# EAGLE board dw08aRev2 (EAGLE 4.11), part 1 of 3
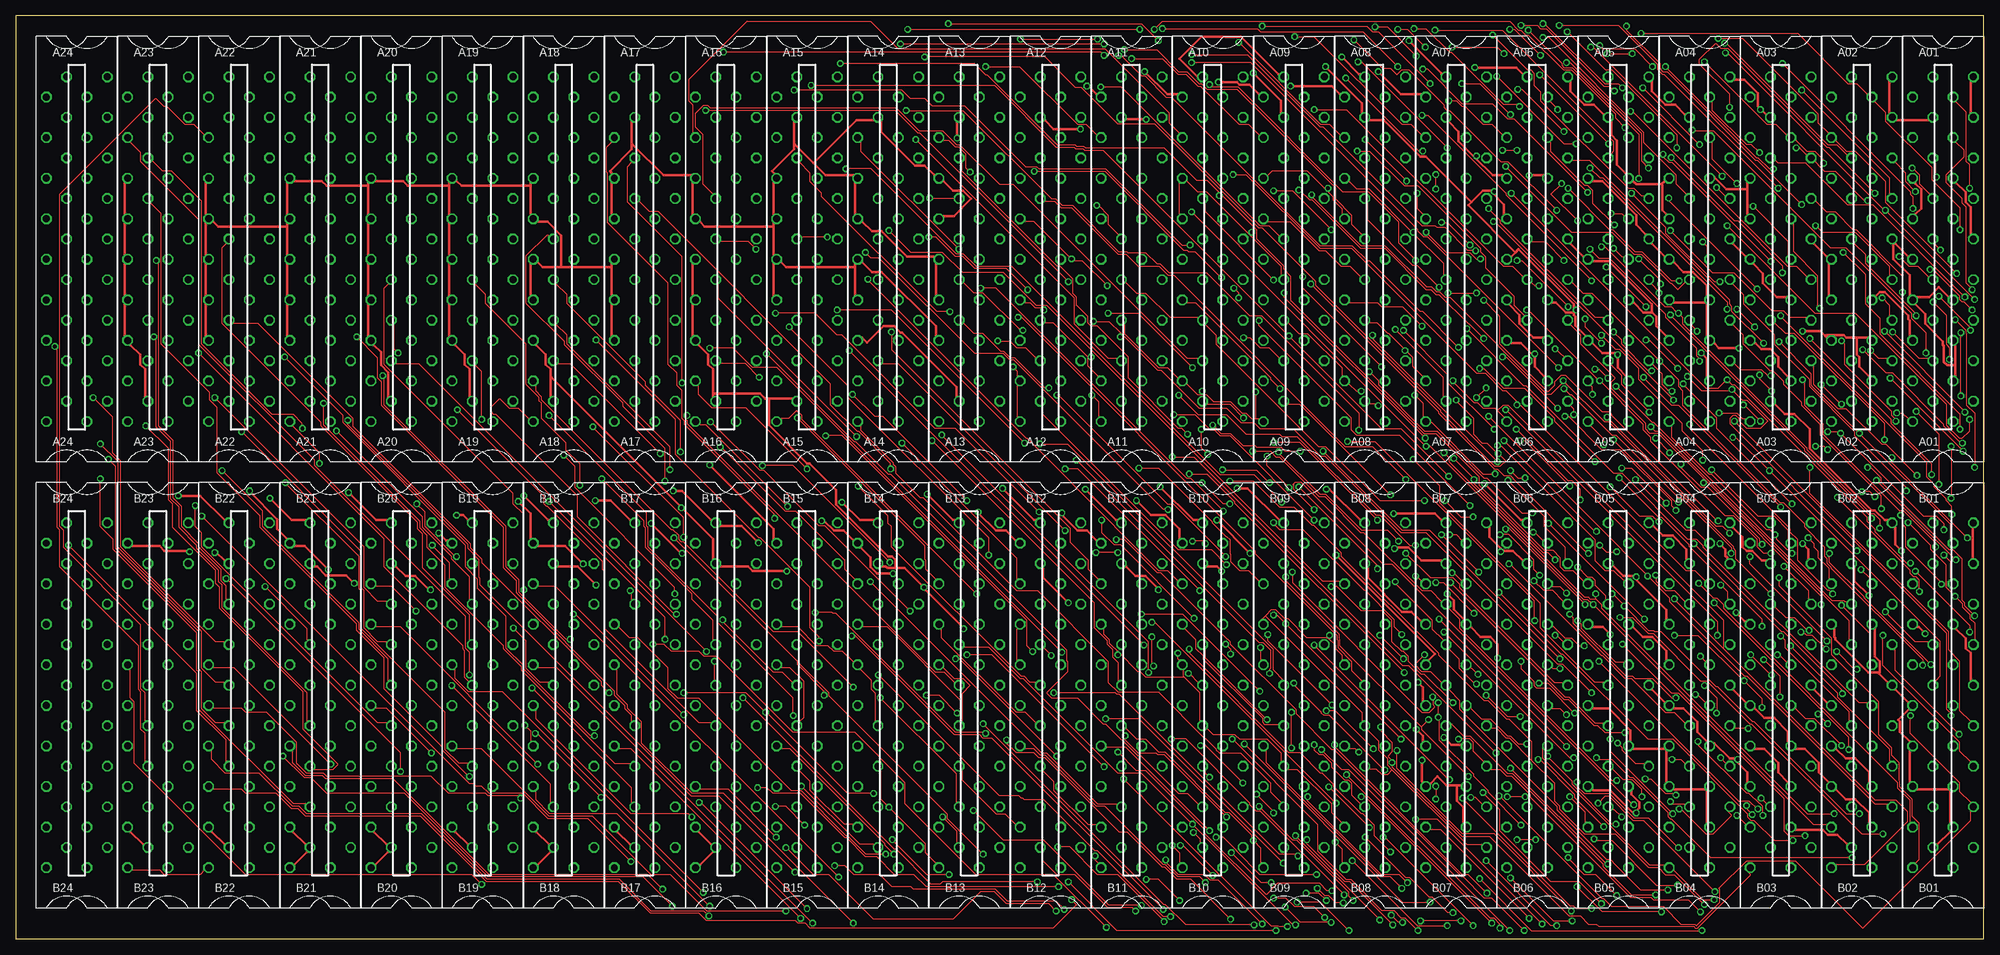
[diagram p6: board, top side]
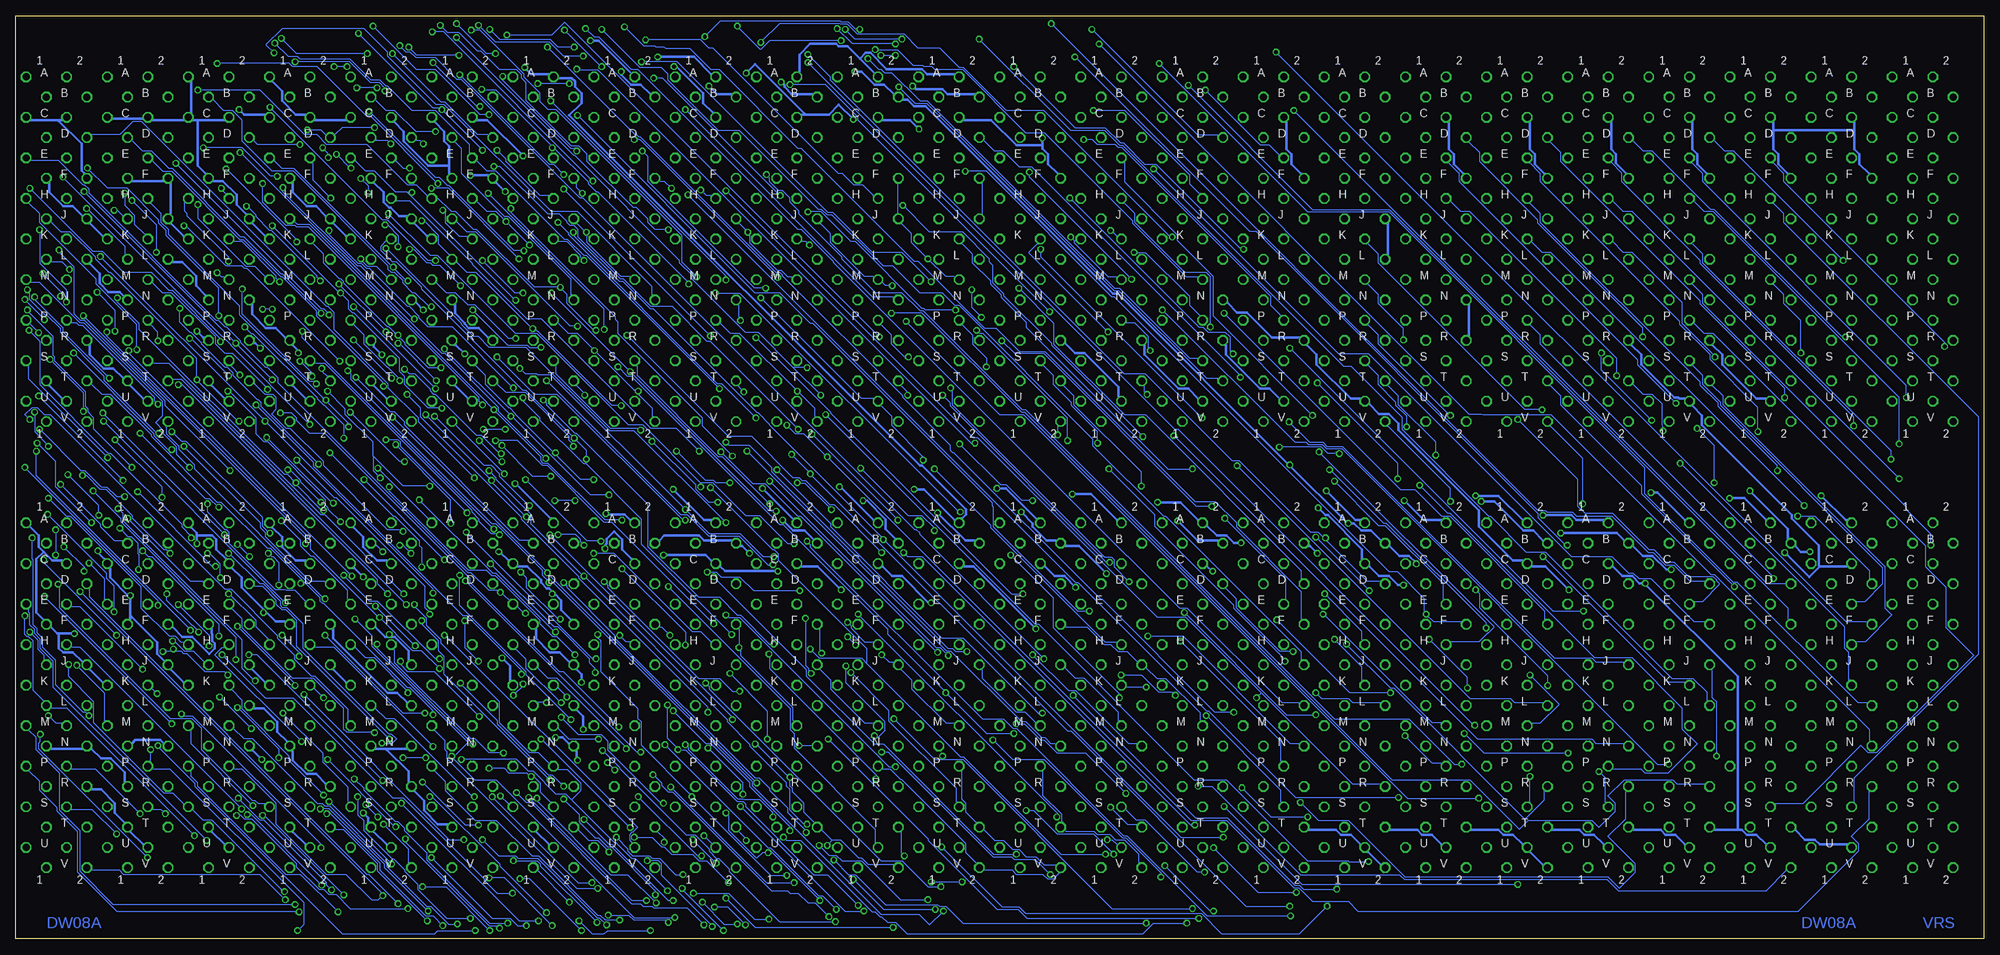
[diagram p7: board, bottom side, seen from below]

Size 307.98 x 144.46 mm. Coordinates in mm from the lower left corner, seen from the top.
Outline: 0,0 307.98,0 307.98,144.46 0,144.46 0,0
Copper layers (1*16): Top 0.035mm / dielectric 1.5mm / Bottom 0.035mm
Design rules "sierraproto": minimum track width 6mil, minimum drill 24mil, track to track 6mil, track to pad 6mil, pad to pad 10mil, via to via 6mil, smd to smd 6mil, copper to edge 25mil, drill to drill 10mil, minimum pad ring 10mil, minimum via ring 8mil, stop-mask expansion 0mil, vias tented up to drill 0mil, thermal gap 10mil
Net classes: 1 supply: width 0.381 mm

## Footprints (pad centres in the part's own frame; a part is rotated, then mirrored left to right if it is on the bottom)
H807 = drill 1.092 octagon: A1 4.763,28.575; A2 -1.587,28.575; B1 1.587,25.4; B2 -4.763,25.4; C1 4.763,22.225; C2 -1.587,22.225; D1 1.587,19.05; D2 -4.763,19.05; E1 4.763,15.875; E2 -1.587,15.875; F1 1.587,12.7; F2 -4.763,12.7; H1 4.763,9.525; H2 -1.587,9.525; J1 1.587,6.35; J2 -4.763,6.35; K1 4.763,3.175; K2 -1.587,3.175; L1 1.587,0; L2 -4.763,0; M1 4.763,-3.175; M2 -1.587,-3.175; N1 1.587,-6.35; N2 -4.763,-6.35; P1 4.763,-9.525; P2 -1.587,-9.525; R1 1.587,-12.7; R2 -4.763,-12.7; S1 4.763,-15.875; S2 -1.587,-15.875; T1 1.587,-19.05; T2 -4.763,-19.05; U1 4.763,-22.225; U2 -1.587,-22.225; V1 1.587,-25.4; V2 -4.763,-25.4

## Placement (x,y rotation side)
A01  M903  [H807]  301.62,106.36 0 top
A02  M903  [H807]  288.93,106.36 0 top
A03  M903  [H807]  276.23,106.36 0 top
A04  M903  [H807]  263.52,106.36 0 top
A05  M903  [H807]  250.82,106.36 0 top
A06  M907  [H807]  238.12,106.36 0 top
A07  M651  [H807]  225.43,106.36 0 top
A08  M651  [H807]  212.72,106.36 0 top
A09  M651  [H807]  200.03,106.36 0 top
A10  M651  [H807]  187.32,106.36 0 top
A11  M651  [H807]  174.62,106.36 0 top
A12  M651  [H807]  161.93,106.36 0 top
A13  W011  [H807]  149.22,106.36 0 top
A14  W011  [H807]  136.53,106.36 0 top
A15  W011  [H807]  123.83,106.36 0 top
A16  W011  [H807]  111.12,106.36 0 top
A17  W011  [H807]  98.42,106.36 0 top
A18  W011  [H807]  85.72,106.36 0 top
A19  W011  [H807]  73.03,106.36 0 top
A20  W011  [H807]  60.33,106.36 0 top
A21  W011  [H807]  47.62,106.36 0 top
A22  W011  [H807]  34.92,106.36 0 top
A23  W011  [H807]  22.23,106.36 0 top
A24  H807  [H807]  9.53,106.36 0 top
B01  M903  [H807]  301.62,36.51 0 top
B02  M903  [H807]  288.93,36.51 0 top
B03  M903  [H807]  276.23,36.51 0 top
B04  M903  [H807]  263.52,36.51 0 top
B05  M903  [H807]  250.82,36.51 0 top
B06  M101  [H807]  238.12,36.51 0 top
B07  M907  [H807]  225.43,36.51 0 top
B08  M651  [H807]  212.72,36.51 0 top
B09  M651  [H807]  200.03,36.51 0 top
B10  M651  [H807]  187.32,36.51 0 top
B11  M651  [H807]  174.62,36.51 0 top
B12  M651  [H807]  161.93,36.51 0 top
B13  M651  [H807]  149.22,36.51 0 top
B14  M651  [H807]  136.53,36.51 0 top
B15  M651  [H807]  123.83,36.51 0 top
B16  M517  [H807]  111.12,36.51 0 top
B17  M517  [H807]  98.42,36.51 0 top
B18  M517  [H807]  85.72,36.51 0 top
B19  M517  [H807]  73.03,36.51 0 top
B20  M517  [H807]  60.33,36.51 0 top
B21  M517  [H807]  47.62,36.51 0 top
B22  M517  [H807]  34.92,36.51 0 top
B23  M517  [H807]  22.23,36.51 0 top
B24  H807  [H807]  9.53,36.51 0 top

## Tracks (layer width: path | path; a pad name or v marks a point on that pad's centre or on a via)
-15V  (via drill 0.61)
  Top 0.381: v126.11,65.41 126.49,65.41 128.02,63.88 129.54,63.88 131.06,62.36 B14.B2 132.21,61.21 133.73,59.69 133.73,58.17 134.75,57.15 v137.29,57.15 | v163.7,66.67 163.7,66.29 166.12,63.88 167.64,63.88 169.16,62.36 B11.B2 | v175.39,68.58 177.67,66.29 179.96,66.29 182.12,64.14 182.12,62.61 B10.B2 | v193.17,60.33 v187.96,65.53 | v150.62,66.8 150.62,66.67 153.42,63.88 154.94,63.88 156.46,62.36 B12.B2 | v167.64,133.48 167.89,133.48 169.16,132.21 A11.B2 | v176.66,135.76 180.21,132.21 181.86,132.21 A10.B2 | v199.52,133.48 205.99,133.48 207.26,132.21 A08.B2 | v213.23,135.76 216.79,132.21 219.96,132.21 A07.B2 | v188.21,134.11 191.13,134.11 191.52,133.73 193.04,133.73 194.56,132.21 A09.B2 | v88.77,58.67 85.98,61.47 81.66,61.47 B18.B2 80.52,62.61 80.52,66.55 v78.61,68.45 | v104.27,60.33 104.14,60.33 v99.44,65.02 | v27.18,60.58 27.05,60.71 23.24,60.71 22.48,61.47 18.16,61.47 B23.B2 | v48.9,57.78 45.21,61.47 43.56,61.47 B21.B2 42.42,62.61 40.89,64.14 40.89,65.66 36.58,69.98 v36.58,70.1 | v66.17,63.5 67.31,62.36 67.56,62.36 B19.B2 | v108.58,74.17 118.62,64.14 118.62,62.61 B15.B2
  Bottom 0.381: v126.11,65.41 123.06,62.36 119.76,62.36 B15.B2 | v137.29,57.15 141.6,61.47 143.76,61.47 B13.B2 145.16,62.36 146.69,62.36 148.84,64.52 148.84,65.02 v150.62,66.8 | B08.B2 207.26,62.36 206.5,63.12 201.04,63.12 200.28,62.36 195.96,62.36 B09.B2 194.56,61.47 194.31,61.47 v193.17,60.33 | v163.7,66.67 159.38,62.36 157.86,62.36 B12.B2 | v175.39,68.58 174.75,68.58 171.83,65.66 171.83,64.14 170.31,62.61 B11.B2 | v187.96,65.53 186.31,63.88 184.53,63.88 B10.B2 | v167.64,133.48 167.13,132.97 162.94,132.97 162.18,132.21 157.86,132.21 A12.B2 | v176.66,135.76 175.64,135.76 173.61,133.73 172.09,133.73 170.56,132.21 A11.B2 169.16,131.32 168.4,131.32 167.39,130.3 165.61,130.3 136.27,100.97 135.51,100.97 108.65,74.11 | v199.52,133.48 198.25,132.21 195.96,132.21 A09.B2 | v213.23,135.76 213.23,135.25 211.71,133.73 210.19,133.73 208.66,132.21 A08.B2 | v188.21,134.11 187.71,133.6 187.71,133.35 186.56,132.21 183.26,132.21 A10.B2 | v88.77,58.67 88.77,58.8 89.92,59.94 91.44,59.94 92.96,61.47 B17.B2 94.36,62.36 95.89,63.88 97.41,63.88 98.55,65.02 v99.44,65.02 99.82,65.28 108.65,74.11 | v104.27,60.33 105.41,61.47 105.66,61.47 B16.B2 | v27.18,60.58 28.57,60.58 29.46,61.47 B22.B2 30.61,62.61 30.61,64.14 v36.58,70.1 | v48.9,57.78 49.66,57.78 51.82,59.94 53.34,59.94 54.86,61.47 B20.B2 56.26,62.36 57.4,63.5 v66.17,63.5 | v78.61,68.45 76.58,68.45 72.01,63.88 70.48,63.88 68.96,62.36 B19.B2 | v108.58,74.17 108.65,74.11
A06U1  (via drill 0.61)
  Top 0.152: 205.1,117.22 202.18,120.14 196.6,120.14 195.96,119.51 A09.F2 | 205.1,117.22 206.12,116.2 206.12,115.7 207.52,114.3 207.52,113.41 A08.J2 | v205.36,117.47 205.1,117.22 | 218.69,110.49 211.84,117.35 209.93,117.35 208.66,118.62 A08.F2 | 218.69,110.49 223.39,105.79 223.39,103.89 A07.M2 | v219.33,116.71 219.33,114.3 220.22,113.41 A07.J2 | A09.J2 195.96,112.27 199.39,112.27 203.96,107.7 204.98,107.7 207.39,105.28 208.79,105.28 210.44,103.63 A08.M2 | v218.69,110.62 218.69,110.49 | v233.55,71.75 239.14,66.17 239.14,64.64 242.44,61.34 242.44,59.44 B06.C1 | v243.84,82.04 243.84,82.93 243.33,83.44 A06.U1 | A12.J2 157.86,112.27 159.38,112.27 v165.23,106.43 165.61,106.17 166.88,106.17 v170.81,102.23 | A11.M2 173.74,102.74 175.39,101.09 176.78,101.09 180.59,97.28 185.04,97.28 A10.P2 186.18,96.14 187.83,94.49 187.83,93.09 203.84,77.09 204.98,77.09 213.49,68.58 v220.47,68.58 | A10.J2 182.12,113.41 182.12,118.36 A10.F2 183.26,118.62 184.91,116.97 186.31,116.97 193.04,110.24 | 193.04,110.24 197.99,105.28 197.99,103.89 A09.M2 | v228.09,66.04 226.19,66.04 v223.65,68.58 | 193.04,110.24 v193.42,110.62
  Bottom 0.152: v205.36,117.47 206.5,118.62 207.26,118.62 A08.F2 | A10.M2 186.44,103.63 187.2,103.63 188.21,104.65 188.85,104.65 193.17,108.97 193.17,110.36 v193.42,110.62 194.82,112.01 A09.J2 | 218.82,110.62 220.22,112.01 A07.J2 | 218.82,110.62 218.57,110.36 218.57,108.97 213.23,103.63 211.84,103.63 A08.M2 | v219.33,116.71 220.22,117.6 220.22,118.36 A07.F2 | 218.82,110.62 v218.69,110.62 | v243.84,82.04 v233.55,71.75 233.3,71.37 233.3,71.25 v228.09,66.04 | A12.J2 156.72,113.41 156.72,118.36 A12.F2 | A12.M2 161.04,103.63 162.43,103.63 v165.23,106.43 167.77,108.97 167.77,110.36 169.42,112.01 A11.J2 169.93,113.41 169.93,118.36 A11.F2 | A10.J2 182.12,112.01 180.47,110.36 180.47,108.97 175.13,103.63 173.74,103.63 A11.M2 172.34,102.74 171.83,102.23 v170.81,102.23 | v220.47,68.58 v223.65,68.58
A06V1  (via drill 0.61)
  Top 0.152: v218.95,85.09 220.22,83.82 220.22,81.66 A07.V2 221.36,81.03 229.62,72.77 v231.52,72.77 | 217.42,92.2 218.57,91.06 218.57,89.66 220.22,88.01 A07.T2 | 217.42,92.2 214.88,94.74 214.76,94.74 213.11,96.39 211.84,96.39 A08.P2 | v217.42,92.08 217.42,92.2 | A09.P2 199.14,96.39 200.79,94.74 202.18,94.74 207.52,89.41 207.52,88.01 A08.T2 208.66,86.87 209.8,85.72 v210.57,85.72 | A12.V2 156.72,81.66 156.72,86.61 A12.T2 156.72,88.01 156.72,88.9 v156.08,89.53 | v168.4,85.09 169.42,84.07 169.42,81.66 A11.V2 | 167.77,91.06 162.43,96.39 161.04,96.39 A12.P2 | 167.77,91.06 167.77,89.66 169.42,88.01 A11.T2 | 194.06,81.41 193.42,81.41 192.53,82.3 191.9,82.3 190.12,84.07 187.45,84.07 186.31,85.22 185.67,85.22 | 194.06,81.41 194.56,81.41 A09.V2 | 185.67,85.22 184.91,85.22 183.26,86.87 A10.T2 181.86,87.76 180.21,89.41 178.82,89.41 173.48,94.74 173.48,96.14 A11.P2 | 194.06,81.41 v194.06,85.6 | 167.77,91.06 v168.28,91.06 | 185.67,85.22 v185.67,85.72
  Bottom 0.152: 210.82,85.47 v217.42,92.08 220.09,94.74 221.49,94.74 223.14,96.39 A07.P2 | 210.82,85.47 208.41,83.06 208.41,81.66 A08.V2 | v218.95,85.09 218.95,85.34 220.22,86.61 A07.T2 | v231.52,72.77 A06.V1 | A10.V2 183.01,81.66 183.01,83.06 v185.67,85.72 194.69,94.74 196.09,94.74 197.74,96.39 A09.P2 | v168.4,85.09 168.4,85.6 169.42,86.61 A11.T2 | v156.08,89.53 156.08,90.93 158.24,93.09 158.24,94.49 159.89,96.14 A12.P2 | v194.06,85.6 194.82,86.36 194.82,86.61 A09.T2 | v168.28,91.06 168.91,91.06 170.94,93.09 170.94,94.49 172.59,96.14 A11.P2 | v210.57,85.72 210.82,85.47
B07U1  (via drill 0.61)
  Top 0.152: B14.M2 134.49,34.04 134.49,38.48 133.86,39.12 133.86,40.51 132.21,42.16 B14.J2 131.06,43.31 129.41,44.96 128.02,44.96 127.13,45.85 125.35,45.85 122.43,48.77 119.76,48.77 B15.F2 | B15.J2 119.76,42.42 121.16,42.42 123.32,40.26 123.32,34.67 122.68,34.04 B15.M2 | B12.J2 156.72,43.56 156.72,48.51 B12.F2 | 148.08,37.08 148.08,38.35 149.35,39.62 148.21,40.77 146.81,40.77 145.16,42.42 B13.J2 | 148.08,37.08 148.08,34.04 B13.M2 | 148.08,37.08 136.4,48.77 132.46,48.77 B14.F2 | 215.39,26.42 214.63,25.65 213.87,25.65 212.98,26.54 211.84,26.54 B08.P2 | 215.39,26.42 214.63,27.18 214.63,28.19 213.23,29.59 213.23,30.99 211.58,32.64 B08.M2 210.69,34.04 210.69,35.43 195.58,50.55 | 215.39,26.42 227.08,14.73 229.49,14.73 B07.U1 | B09.M2 197.74,33.53 195.45,33.53 195.07,33.91 195.07,34.54 185.8,43.81 185.8,44.32 184.66,45.47 184.66,46.86 183.01,48.51 B10.F2 | v206.5,15.11 207.52,14.1 207.52,11.81 B08.V2 | B08.T2 207.52,18.16 205.87,19.81 205.87,21.21 200.53,26.54 199.14,26.54 B09.P2 197.99,27.69 197.99,29.08 195.83,31.24 191.52,31.24 190.75,32 187.32,32 186.44,32.89 B10.M2 185.29,34.04 185.29,38.48 182.88,40.89 | v194.82,45.59 194.82,43.56 B09.J2 | 205.23,47.12 202.06,47.12 199.14,50.04 198.63,50.04 197.23,51.44 196.47,51.44 195.58,50.55 | 205.23,47.12 205.36,47.12 206.5,45.97 206.5,45.47 207.52,44.45 207.52,43.56 B08.J2 | 195.58,50.55 194.94,49.91 B09.F2 | v205.61,47.5 205.23,47.12 | B09.V2 194.82,11.81 194.82,14.22 v193.68,15.37 193.42,15.75 193.42,16.26 189.87,19.81 189.23,19.81 179.83,29.21 178.82,29.21 176.78,31.24 175.39,31.24 173.74,32.89 B11.M2
  Top 0.152: 182.88,40.89 182.75,41.02 182.75,42.16 B10.J2 182.12,43.56 181.86,43.81 v181.86,44.7 | 172.72,44.7 175.64,41.78 176.02,41.78 176.91,40.89 182.88,40.89 | 172.72,44.7 171.2,46.23 171.2,46.74 170.31,47.62 170.31,48.51 B11.F2 | 172.72,44.7 v172.47,44.45 | B13.F2 144.91,48.51 144.91,47.12 156.59,35.43 157.99,35.43 159.64,33.78 B12.M2
  Bottom 0.152: B15.M2 122.68,34.04 122.68,35.43 128.02,40.77 129.41,40.77 131.06,42.42 B14.J2 132.46,43.31 134.11,44.96 135.51,44.96 136.65,46.1 137.67,46.1 140.34,48.77 143.76,48.77 B13.F2 | B12.J2 156.72,42.16 156.72,40.77 151.38,35.43 149.99,35.43 148.34,33.78 B13.M2 | B14.M2 135.38,34.04 135.38,35.43 140.72,40.77 142.11,40.77 143.76,42.42 B13.J2 | v206.5,15.11 206.5,15.75 207.52,16.76 B08.T2 | B09.F2 194.82,48.51 v194.82,45.59 194.56,45.21 194.56,44.32 186.44,36.2 186.44,34.29 186.18,34.04 B10.M2 | v205.61,47.5 206.88,48.77 207.26,48.77 B08.F2 | B12.M2 161.04,33.78 162.43,33.78 167.77,39.12 167.77,40.51 169.42,42.16 B11.J2 170.56,43.31 171.32,43.31 v172.47,44.45 | v193.68,15.37 193.68,15.62 194.82,16.76 B09.T2 | B11.M2 173.74,33.78 175.13,33.78 180.47,39.12 180.47,40.51 182.12,42.16 B10.J2 | v181.86,44.7 182.12,44.96 182.12,48.51 B10.F2
B07V1  (via drill 0.61)
  Top 0.152: B14.T2 131.06,17.91 129.67,17.91 124.33,23.24 124.33,24.64 122.68,26.29 B15.P2 | B14.P2 135.38,26.29 135.38,21.84 v136.65,20.57 142.37,14.86 142.37,13.46 144.02,11.81 B13.V2 | B11.T2 169.16,17.91 167.77,17.91 162.43,23.24 162.43,24.64 160.78,26.29 B12.P2 | B13.P2 148.08,26.29 148.08,24.89 153.42,19.56 154.81,19.56 156.46,17.91 B12.T2 | v180.97,14.61 182.12,13.46 182.12,11.81 B10.V2 | v186.82,25.27 186.18,25.91 186.18,26.29 B10.P2 | v221.36,5.71 217.04,5.71 v192.28,30.48 | v168.91,12.95 168.91,12.32 169.42,11.81 B11.V2
  Bottom 0.152: B14.V2 132.21,11.81 132.21,13.21 134.37,15.37 135.76,15.37 136.65,16.26 138.68,16.26 139.19,16.76 143.51,16.76 143.76,17.02 B13.T2 144.27,18.16 144.27,19.43 147.19,22.35 147.19,26.29 B13.P2 | B12.P2 159.89,26.29 159.89,21.84 159.26,21.21 159.26,19.81 157.61,18.16 B12.T2 156.46,17.02 154.81,15.37 153.42,15.37 152.02,13.97 151,13.97 149.86,12.83 148.34,12.83 147.07,11.56 145.16,11.56 B13.V2 144.53,10.41 145.67,9.27 146.43,9.27 147.19,10.03 151.38,10.03 152.02,10.67 156.46,10.67 B12.V2 157.61,11.81 159.26,13.46 159.26,14.86 169.29,24.89 169.42,24.89 171.07,26.54 172.34,26.54 B11.P2 | v136.65,20.57 133.99,17.91 132.46,17.91 B14.T2 | 180.21,15.37 178.82,15.37 176.02,12.57 175.51,12.57 174.5,11.56 170.56,11.56 B11.V2 | 180.21,15.37 181.86,17.02 B10.T2 183.01,18.16 184.66,19.81 184.66,21.21 186.44,22.99 186.44,23.5 186.82,23.88 v186.82,25.27 187.2,25.53 192.15,30.48 v192.28,30.48 | 180.21,15.37 v180.97,14.61 | v221.36,5.71 226.31,10.67 B07.V1 | v168.91,12.95 169.42,13.46 169.42,16.76 B11.T2
GND  (via drill 0.61)
  Top 0.381: B16.V2 107.06,11.56 109.09,13.59 B16.U2 108.84,14.73 106.81,16.76 B16.T2 | B17.T2 94.11,16.76 96.14,14.73 B17.U2 | B18.V2 81.66,11.56 83.69,13.59 B18.U2 83.44,14.73 81.41,16.76 B18.T2 | B19.T2 68.71,16.76 70.74,14.73 B19.U2 | B20.V2 56.26,11.56 58.29,13.59 B20.U2 58.04,14.73 56.01,16.76 B20.T2 | B21.V2 43.56,11.56 45.59,13.59 B21.U2 45.34,14.73 43.31,16.76 B21.T2 | B23.U2 19.94,14.73 17.91,16.76 B23.T2 | B22.T2 30.61,16.76 32.64,14.73 B22.U2 | 232.66,60.83 232.79,60.71 234.31,60.71 235.84,59.18 B06.C2 | 232.66,60.83 230.63,62.87 230.63,64.39 B07.A1 | B08.C2 211.58,58.04 211.58,56.52 216.92,51.18 218.44,51.18 219.96,49.66 B07.F2 | v215.77,61.09 215.9,61.21 217.93,61.21 219.96,59.18 223.14,59.18 B07.C2 | v232.41,60.58 232.66,60.83 | 225.55,24 226.31,24 B07.R1 | 225.55,24 223.9,24 222.5,25.4 221.36,24.26 B07.R2 220.22,24.51 220.09,24.64 v220.09,27.94 | v223.52,31.5 224.66,30.35 226.31,30.35 B07.N1 | B07.T1 226.57,18.16 226.57,20.57 225.55,21.59 225.55,24 | v219.46,40.13 220.22,39.37 220.22,37.21 B07.L2 | v231.9,43.94 231.9,46.1 230.76,47.24 229.24,47.24 227.71,48.77 B07.F1 226.69,49.91 225.04,51.56 225.04,52.96 v224.03,53.98 | v219.2,32.77 220.22,31.75 220.22,30.86 B07.N2 | v188.72,57.53 187.96,58.29 186.44,58.29 B10.C2 | v164.72,52.58 160.78,56.52 160.78,58.04 B12.C2 | v178.82,54.61 178.82,54.74 176.78,56.77 175.26,56.77 173.74,58.29 B11.C2 | v52.96,55.63 51.69,56.9 48.51,56.9 47.12,58.29 46.74,58.29 B21.C2 | v64.9,54.61 64.64,54.61 62.48,56.77 60.96,56.77 59.44,58.29 B20.C2 | 137.67,58.04 139.06,58.04 v142.11,54.99 142.37,54.61 148.34,48.64 v148.34,48.51
  Top 0.381: 137.67,58.04 136.4,58.04 136.14,58.29 135.64,58.29 B14.C2 | A16.L2 105.92,105.66 105.92,100.71 A16.N2 105.92,99.31 105.92,94.36 A16.R2 106.81,92.96 108.33,91.44 108.33,89.92 109.09,89.15 109.09,85.34 | 109.09,85.34 109.09,84.84 A16.U2 | 117.86,84.58 117.22,84.58 116.46,85.34 109.09,85.34 | 117.86,84.58 121.54,84.58 A15.U2 | A13.U2 147.19,84.84 147.19,86.36 138.68,94.87 138.43,94.87 137.41,95.89 135.76,95.89 133.22,93.34 132.46,94.11 A14.R2 | 137.67,58.04 137.67,59.31 137.16,59.82 136.53,59.82 128.4,67.94 128.4,70.23 124.21,74.42 123.83,74.42 117.86,80.39 117.86,84.58 | v206.63,60.07 222.12,44.58 221.11,43.56 B07.J2 | B03.K1 281.43,38.99 283.46,36.96 B02.L2 | v290.07,53.72 287.78,56.01 287.78,58.04 B02.C2 | v295.15,60.71 294.13,61.72 294.13,64.39 B02.A1 292.99,65.53 292.48,65.53 290.96,67.06 290.45,67.06 280.8,76.71 280.8,79.76 278.38,82.17 276.86,82.17 275.34,83.69 A03.U2 | B01.C1 306.32,59.44 306.32,64.39 B01.A1 | v298.83,47.75 297.81,48.77 297.56,48.77 B01.F2 | B01.K1 305.94,40.39 305.94,44.7 305.18,45.47 305.18,46.99 303.66,48.51 B01.F1 | 291.59,41.53 292.99,40.13 B02.K1 294.13,38.99 296.16,36.96 B01.L2 294.64,34.29 294.89,34.04 294.89,32.38 296.42,30.86 B01.N2 296.42,29.46 296.42,24.51 B01.R2 297.56,23.37 302.51,23.37 B01.R1 302.77,23.11 302.77,18.16 B01.T1 302.77,16.76 300.74,14.73 B01.U2 | 291.59,41.53 291.46,41.66 289.94,41.66 284.73,46.86 284.73,47.12 284.61,47.24 284.61,48.51 B02.F2 | B02.R1 290.07,24.51 290.07,26.04 287.91,28.19 286.38,28.19 284.86,29.72 B02.N2 | B02.F1 290.96,48.51 290.96,44.2 291.72,43.43 291.72,41.66 291.59,41.53
  Top 0.381: v279.65,61.85 280.54,60.96 280.54,59.44 B03.C1 | v269.24,51.05 270.64,49.66 270.76,49.66 B03.F2 | v266.7,61.85 267.59,60.96 267.59,59.94 267.84,59.69 267.84,59.44 B04.C1 | 253.37,56.39 252.98,56.77 251.59,56.77 249.94,58.42 B05.C2 | 253.37,56.39 258.32,51.44 258.32,49.91 B04.F2 | 253.37,56.39 v253.62,56.64 | B04.C2 261.49,59.44 261.49,60.96 259.33,63.12 257.81,63.12 256.29,64.64 B05.A1 | B03.C2 273.94,59.18 273.3,59.18 271.78,60.71 270.89,60.71 270.26,61.34 270.26,62.87 268.73,64.39 B04.A1 | B05.K1 256.03,38.99 258.06,36.96 B04.L2 259.46,36.07 260.99,36.07 263.14,33.91 263.14,32.38 264.67,30.86 B04.N1 265.81,30.61 268.22,28.19 268.86,28.19 269.24,27.81 | v249.56,47.62 248.41,48.77 246.76,48.77 B05.F2 | B04.J2 258.32,43.56 258.32,45.09 256.16,47.24 254.63,47.24 253.11,48.77 B05.F1 | 253.49,19.81 253.24,19.56 249.56,23.24 246.89,23.24 246.76,23.37 B05.R2 | 253.49,19.81 254.13,20.45 254.13,21.34 252.86,22.61 252.86,23.11 B05.R1 | 253.49,19.81 v253.62,19.68 | B03.T1 278.51,17.02 282.83,17.02 283.59,16.26 285.12,16.26 286.64,14.73 B02.U2 | B03.N2 272.16,29.72 273.69,29.72 275.84,27.56 275.84,26.04 277.37,24.51 B03.R1 | B05.L2 246.76,36.07 249.3,36.07 252.73,32.64 252.73,30.86 B05.N1 253.11,29.72 258.06,29.72 B04.N2 258.32,29.46 258.32,24.51 B04.R2 259.46,23.37 264.41,23.37 B04.R1 264.67,23.11 264.67,18.16 B04.T1 | B04.K1 268.73,38.99 270.76,36.96 B03.L2 272.16,36.07 273.69,34.54 275.21,34.54 277.37,32.38 277.37,30.86 B03.N1 278.51,29.72 280.04,29.72 282.19,27.56 282.19,26.04 283.72,24.51 B02.R2 284.86,23.37 286.38,21.84 287.91,21.84 290.07,19.68 290.07,18.16 B02.T1
  Top 0.381: 269.24,27.81 271.02,26.04 271.02,24.51 B03.R2 | 269.24,27.81 v269.49,28.07 | A06.R1 239.01,94.11 237.49,94.11 235.33,96.27 235.33,97.66 233.68,99.31 A06.N2 | 237.49,91.31 237.74,91.06 237.74,89.53 239.27,88.01 A06.T1 | 237.49,91.31 235.59,93.22 234.06,93.22 A06.R2 | 237.49,91.31 v237.74,91.57 | 228.35,122.3 225.81,124.84 225.81,126.36 224.28,127.89 A07.C2 | 228.35,122.3 231.14,119.51 232.66,119.51 A06.F2 | 228.35,122.3 v228.6,122.56 | A05.T1 252.09,88.01 250.7,89.41 v250.7,91.44 250.32,91.69 248.28,91.69 246.76,93.22 A05.R2 245.75,94.36 244.09,96.01 244.09,97.41 243.84,97.66 243.84,98.04 | 234.7,107.44 235.2,107.95 243.84,99.31 243.84,98.42 | 234.7,107.44 234.06,106.81 A06.L2 | 243.84,98.42 243.84,98.04 | 243.84,98.42 v244.22,98.42 | 231.14,116.71 230.76,117.09 229.62,117.09 227.84,115.32 | 231.14,116.71 232.92,114.94 232.92,113.41 A06.J2 | 227.84,115.32 227.33,114.81 234.7,107.44 | 227.84,115.32 220.73,122.43 219.84,122.43 214.12,128.14 211.84,128.14 A08.C2 210.69,129.29 210.69,130.81 v204.98,136.53 | 231.14,116.71 v231.39,116.97 | A06.N1 240.41,99.57 241.05,99.57 242.57,98.04 243.84,98.04 | v279.65,95.12 282.45,95.12 283.21,94.36 | 283.21,94.36 283.46,94.11 A02.R2 | 288.16,94.11 286.51,94.11 286.13,94.49 283.34,94.49 283.21,94.36 | 288.16,94.11 289.81,94.11 A02.R1 | 288.16,94.11 288.16,91.44 288.54,91.06 288.54,89.53 290.07,88.01 A02.T1 | 303.53,89.79 303.53,88.01 A01.T1 | 303.53,89.79 303.53,92.96 A01.R1 | A01.N2 297.56,100.46 299.47,100.46 300.99,101.98 302.51,100.46 A01.N1 | A01.L2 296.16,106.81 294.13,108.84 A02.K1 293.88,108.84 293.88,106.43 296.42,103.89 296.42,100.71 A01.N2
  Top 0.381: A01.F2 297.31,118.36 297.31,118.24 298.2,117.35 298.2,114.3 297.31,113.41 A01.J2 | A01.K1 305.94,110.24 305.94,114.55 305.18,115.32 305.18,116.84 303.66,118.36 A01.F1 | 303.53,89.79 302.26,89.79 301.75,90.3 301.75,92.84 301.62,92.96 301.62,93.47 298.83,96.27 298.83,97.79 297.31,99.31 A01.N2 | A01.R2 296.42,94.36 296.42,96.77 296.16,97.03 296.16,97.54 292.48,101.22 291.72,101.22 A02.N1 | A01.C2 299.34,128.14 294.39,128.14 A02.C1 293.24,129.29 293.24,134.24 A02.A1 | A01.A1 305.94,134.24 305.94,129.29 A01.C1 | A05.A1 256.03,134.24 256.03,132.72 258.19,130.56 259.71,130.56 261.24,129.03 A04.C2 | A03.C2 273.94,129.03 273.18,129.79 v273.05,129.79 272.8,130.18 272.67,130.3 272.67,132.33 270.51,134.49 268.99,134.49 A04.A1 | A03.R2 272.16,93.22 272.29,93.22 273.18,92.33 274.57,92.33 275.84,91.06 275.84,89.53 277.37,88.01 A03.T1 | A04.N2 259.46,99.57 264.41,99.57 A04.N1 | A04.N1 264.67,99.31 264.67,94.36 A04.R1 265.81,93.22 266.57,92.46 v269.75,92.46 | v263.78,91.69 264.67,90.81 264.67,88.01 A04.T1 | A03.K1 281.43,108.84 283.46,106.81 A02.L2 283.72,105.66 283.72,100.71 A02.N2 | A04.K1 268.73,108.84 270.76,106.81 A03.L2 271.91,105.66 273.43,104.14 273.43,102.62 275.59,100.46 277.11,100.46 A03.N1 | 271.02,117.35 271.02,113.41 A03.J2 | 271.02,117.35 271.02,118.36 A03.F2 | A06.A1 243.33,134.24 243.33,132.72 245.49,130.56 247.01,130.56 248.54,129.03 A05.C2 249.68,127.89 249.68,125.86 250.57,124.97 250.57,121.16 251.97,119.76 A05.F1 253.11,118.62 253.62,118.11 257.56,118.11 | 256.03,98.04 256.16,98.04 256.79,97.41 256.79,95.89 258.32,94.36 A04.R2
  Top 0.381: 256.03,98.04 254.76,98.04 253.24,99.57 253.11,99.57 A05.N1 | A06.K1 243.33,108.84 245.36,106.81 A05.L2 246.76,106.05 249.3,106.05 256.03,99.31 256.03,98.04 | 257.56,118.11 258.06,118.62 A04.F2 | A05.F2 246.76,118.62 248.28,118.62 253.62,113.28 253.62,111.76 255.14,110.24 A05.K1 256.03,108.84 258.06,106.81 A04.L2 259.46,105.92 260.99,104.39 262.51,104.39 264.67,102.23 264.67,100.71 A04.N1 | 257.56,118.11 257.68,117.98 257.68,114.05 258.32,113.41 A04.J2 | 271.02,117.35 267.72,117.35 265.81,119.25 A04.F1 | v236.85,119.51 239.01,119.51 A06.F1 | A21.R2 42.42,94.36 42.42,99.31 A21.N2 42.42,100.71 42.42,105.66 A21.L2 42.42,107.06 42.42,111.51 | 42.42,111.51 42.42,112.01 A21.J2 42.42,113.41 42.42,118.36 A21.F2 43.56,118.62 47.88,118.62 48.64,117.86 55.12,117.86 | A22.R2 29.72,94.36 29.72,99.31 A22.N2 29.72,100.71 29.72,105.66 A22.L2 29.72,107.06 29.72,112.01 A22.J2 | A22.F2 29.72,118.36 29.72,113.41 A22.J2 | A23.U2 20.19,84.84 20.19,89.15 19.43,89.92 19.43,91.44 17.91,92.96 A23.R2 17.02,94.36 17.02,99.31 A23.N2 17.02,100.71 17.02,105.66 A23.L2 17.02,107.06 17.02,112.01 A23.J2 17.02,113.41 17.02,118.36 A23.F2 | 42.42,111.51 31.62,111.51 30.86,112.27 A22.J2 | v31.11,60.45 31.37,60.45 32.64,59.18 B22.C2 | A20.U2 58.29,84.84 58.29,88.65 57.15,89.79 57.15,91.82 56.01,92.96 A20.R2 55.12,94.36 55.12,99.31 A20.N2 55.12,100.71 55.12,105.66 A20.L2 55.12,107.06 55.12,112.01 A20.J2 55.12,113.41 55.12,117.86 | 55.12,117.86 55.12,118.36 A20.F2 56.26,118.62 60.58,118.62 61.34,117.86 67.82,117.86 | A13.J2 145.16,113.16 146.81,113.16 149.48,115.82 148.21,117.09 146.69,117.09 145.16,118.62 A13.F2 143.76,119.51 142.24,121.03 140.72,121.03 135.38,126.36 135.38,127.89 A14.C2 134.24,128.14 131.57,128.14 124.84,121.41
  Top 0.381: v147.32,125.35 147.32,127.89 A13.C2 | v166.62,126.75 162.43,126.75 161.04,128.14 A12.C2 | v176.91,128.27 173.74,128.27 A11.C2 | v193.68,135.51 197.99,131.19 197.99,129.29 A09.C2 | A13.N2 144.02,100.71 144.02,105.66 A13.L2 143.76,106.81 139.45,106.81 135.51,110.74 133.99,110.74 132.46,112.27 A14.J2 131.32,113.41 131.32,118.36 A14.F2 131.06,119.51 126.75,119.51 124.84,121.41 | 131.32,105.16 131.32,105.66 A14.L2 132.46,105.92 133.99,104.39 135.51,104.39 144.02,95.89 144.02,94.36 A13.R2 | 131.32,105.16 131.32,100.71 A14.N2 | A15.N2 118.62,100.71 118.62,105.66 A15.L2 | 118.62,111.51 118.62,107.06 A15.L2 | 118.62,111.51 118.62,112.01 A15.J2 118.62,113.41 118.62,118.36 A15.F2 118.75,119.76 118.36,120.14 121.79,123.57 121.79,124.33 | 121.79,124.33 121.79,127.89 A15.C2 | 131.32,105.16 120.52,105.16 119.76,105.92 A15.L2 | 124.84,121.41 121.92,124.33 121.79,124.33 | 80.52,117.86 80.52,118.36 A18.F2 | 80.52,117.86 80.52,113.41 A18.J2 81.66,112.27 83.19,112.27 85.34,110.11 85.34,105.16 | A19.U2 70.99,84.84 70.99,89.15 70.23,89.92 70.23,91.44 68.71,92.96 A19.R2 67.82,94.36 67.82,99.31 A19.N2 67.82,100.71 67.82,105.66 A19.L2 67.82,107.06 67.82,112.01 A19.J2 67.82,113.41 67.82,117.86 | 67.82,117.86 67.82,118.36 A19.F2 68.96,118.62 69.72,117.86 80.52,117.86 | A17.R2 93.22,94.36 93.22,99.31 A17.N2 93.22,100.71 93.22,105.16 | 93.22,105.16 93.22,105.66 A17.L2 | A17.J2 93.22,113.41 93.22,118.36 A17.F2 93.34,119.76 92.96,120.14 96.39,123.57 96.39,124.33 | 96.39,124.33 96.39,127.89 A17.C2 | 96.39,124.33 96.52,124.33 101.35,119.51 105.66,119.51 A16.F2 105.92,118.36 105.92,113.41 A16.J2 107.06,112.27 107.82,111.51 118.62,111.51
  Top 0.381: v90.81,55.37 87.88,58.29 84.84,58.29 B18.C2 | v120.65,57.53 115.32,57.53 114.55,58.29 110.24,58.29 B16.C2 109.09,59.44 109.09,62.61 104.2,67.5 | 83.69,87.88 83.69,89.15 82.93,89.92 82.93,91.44 81.41,92.96 A18.R2 | 83.69,87.88 83.69,84.84 A18.U2 | A18.N2 80.52,100.71 80.52,105.66 A18.L2 81.66,105.92 82.42,105.16 85.34,105.16 | 104.2,67.5 83.82,87.88 83.69,87.88 | 104.2,67.5 v104.14,67.44 | 93.22,105.16 85.34,105.16
  Bottom 0.381: B17.V2 94.36,11.56 96.39,13.59 B17.U2 97.54,14.73 99.06,16.26 100.58,16.26 101.35,17.02 105.66,17.02 B16.T2 | B19.V2 68.96,11.56 70.99,13.59 B19.U2 72.14,14.73 73.66,16.26 75.18,16.26 75.95,17.02 80.26,17.02 B18.T2 | B23.U2 21.34,14.73 25.65,14.73 26.42,15.49 27.94,15.49 29.46,17.02 B22.T2 | 38.48,17.02 37.85,17.02 37.08,16.26 35.56,16.26 34.04,14.73 B22.U2 | 38.48,17.02 42.16,17.02 B21.T2 | B20.T2 54.86,17.02 50.55,17.02 49.78,16.26 48.26,16.26 46.74,14.73 B21.U2 | B19.T2 67.56,17.02 63.25,17.02 62.48,16.26 60.96,16.26 59.44,14.73 B20.U2 | B17.T2 92.96,17.02 88.65,17.02 87.88,16.26 86.36,16.26 84.84,14.73 B18.U2 | v215.77,61.09 215.77,61.59 215.52,61.85 215.52,62.61 214.38,63.75 213.11,62.48 213.11,60.96 211.58,59.44 B08.C2 | 223.77,54.1 222.63,52.96 222.63,51.44 221.11,49.91 B07.F2 | 223.77,54.1 224.54,54.86 224.92,54.86 225.81,55.75 225.81,56.13 227.97,58.29 229.49,58.29 B07.C1 230.89,59.18 232.28,60.58 v232.41,60.58 | B07.U2 224.54,14.73 226.57,16.76 B07.T1 | v220.09,27.94 220.22,28.07 220.22,29.46 B07.N2 221.36,30.48 222.38,31.5 v223.52,31.5 | v219.46,40.13 219.46,41.4 220.22,42.16 B07.J2 221.36,43.31 222.88,44.83 224.41,44.83 226.57,46.99 226.57,48.51 B07.F1 | v231.9,43.94 230.63,42.67 230.63,40.39 B07.K1 | v219.2,32.77 219.2,34.8 220.22,35.81 B07.L2 | v224.03,53.98 223.9,53.98 223.77,54.1 | v188.72,57.53 196.98,57.53 197.74,58.29 B09.C2 199.14,59.18 200.03,60.07 v206.63,60.07 | v164.72,52.58 165.1,52.58 169.29,56.77 170.81,56.77 172.34,58.29 B11.C2 | v178.82,54.61 182.5,58.29 185.04,58.29 B10.C2 | B20.C2 58.04,58.29 56.52,56.77 54.99,56.77 53.85,55.63 v52.96,55.63 52.7,55.24 38.48,41.02 38.48,17.02
  Bottom 0.381: v64.9,54.61 68.58,58.29 70.74,58.29 B19.C2 72.14,59.18 73.66,59.18 78.99,64.52 78.99,67.06 91.57,79.63 91.57,80.64 93.09,82.17 94.61,82.17 96.14,83.69 A17.U2 97.54,84.58 99.06,84.58 104.39,89.92 104.39,91.44 105.92,92.96 A16.R2 107.06,94.11 111.38,94.11 115.32,98.04 116.84,98.04 118.36,99.57 A15.N2 | v142.11,54.99 143.89,56.77 145.41,56.77 146.94,58.29 B13.C2 | A15.R2 118.62,92.96 118.62,91.44 113.28,86.11 111.76,86.11 110.24,84.58 A16.U2 | A14.R2 131.32,92.96 131.32,91.44 125.98,86.11 124.46,86.11 122.94,84.58 A15.U2 | v148.34,48.51 158.12,58.29 159.64,58.29 B12.C2 | B03.K1 281.69,40.13 283.72,42.16 B02.J2 285.88,44.58 285.88,46.35 289.94,50.42 290.07,50.42 | 290.07,50.42 290.07,49.91 B02.F1 | 290.07,50.42 v290.07,53.72 290.45,53.72 293.24,56.52 293.24,58.04 B02.C1 294.13,59.44 295.15,60.45 v295.15,60.71 | 303.66,60.58 304.42,61.34 304.42,63.12 B01.A1 | 303.66,60.58 302.26,59.18 300.74,59.18 B01.C2 | 301.24,47.75 301.5,47.75 302.51,48.77 B01.F1 303.66,49.91 304.8,51.05 304.8,59.44 303.66,60.58 | 301.24,47.75 v298.83,47.75 | B03.F1 277.37,48.51 277.37,47.75 277.24,47.62 277.24,46.61 276.86,46.23 276.86,45.47 277.75,44.58 280.42,47.24 281.94,47.24 283.46,48.77 B02.F2 | B02.K1 294.39,40.13 296.42,42.16 B01.J2 297.56,43.31 299.08,44.83 300.61,44.83 301.24,45.47 301.24,47.75 | B02.N2 284.86,30.61 285.37,31.11 289.31,31.11 289.81,30.61 B02.N1 | B01.N1 302.51,29.72 297.56,29.72 B01.N2 296.16,29.72 294.64,28.19 293.12,28.19 290.96,26.04 290.96,24.51 B02.R1 | 279.65,63.12 279.65,63.5 280.54,64.39 B03.A1 | 279.65,63.12 v279.65,61.85 | 268.99,51.31 272.67,54.99 272.67,56.52 274.19,58.04 B03.C2 275.08,59.44 276.61,60.96 276.61,62.48 277.24,63.12 279.65,63.12
  Bottom 0.381: 268.99,51.31 267.33,49.66 265.81,49.66 B04.F1 | 268.99,51.31 v269.24,51.05 | 266.32,61.85 266.32,62.87 267.84,64.39 B04.A1 | 266.32,61.85 266.32,61.34 264.16,59.18 262.64,59.18 B04.C2 | 266.32,61.85 v266.7,61.85 | B05.C2 249.94,59.18 251.46,59.18 253.62,61.34 253.62,62.87 255.14,64.39 B05.A1 | v253.62,56.64 255.02,58.04 255.14,58.04 B05.C1 | B04.J2 258.32,42.16 256.29,40.13 B05.K1 | 249.56,47.24 250.19,47.24 251.71,48.77 B05.F1 | 249.56,47.24 248.67,47.24 246.51,45.09 246.51,43.56 B05.J2 | 249.56,47.24 v249.56,47.62 | B05.U2 249.94,14.73 251.97,16.76 B05.T1 252.86,18.16 252.86,18.92 v253.62,19.68 | B06.T1 240.41,17.91 241.94,17.91 244.09,20.07 244.09,21.59 245.62,23.11 B05.R2 246.51,24.51 246.51,26.16 249.94,29.59 249.94,29.72 | B03.U2 275.34,14.73 277.37,16.76 B03.T1 | B02.U2 288.04,14.73 290.07,16.76 B02.T1 290.96,18.16 292.48,19.68 292.48,21.21 294.64,23.37 296.16,23.37 B01.R2 | 249.94,29.72 251.71,29.72 B05.N1 | 249.94,29.72 246.76,29.72 B05.N2 | B03.J2 271.02,42.16 268.99,40.13 B04.K1 | B04.U2 262.64,14.73 264.67,16.76 B04.T1 | B04.R2 259.46,24.26 260.99,25.78 262.51,25.78 264.67,27.94 264.67,29.46 B04.N1 265.56,30.86 267.08,32.38 267.08,33.91 269.24,36.07 270.76,36.07 B03.L2 | v269.49,28.07 270.89,29.46 271.02,29.46 B03.N2 | B04.F2 258.32,48.51 258.32,46.99 249.81,38.48 248.28,38.48 246.76,36.96 B05.L2 | A06.U2 237.24,84.58 239.27,86.61 A06.T1 | A06.N1 239.27,99.31 239.27,97.92 237.74,96.39 237.74,96.27 237.11,95.63 235.59,95.63 234.06,94.11 A06.R2 | v237.74,91.57 239.14,92.96 239.27,92.96 A06.R1 | v228.6,122.56 234.19,128.14 235.84,128.14 A06.C2
  Bottom 0.381: A05.U2 249.94,84.58 251.97,86.61 A05.T1 | v250.7,91.44 251.97,92.71 251.97,92.96 A05.R1 | v244.22,98.42 245.36,99.57 A05.N2 | v231.39,116.97 232.79,118.36 232.92,118.36 A06.F2 234.06,119.51 v236.85,119.51 | v279.65,95.12 278.64,94.11 278.51,94.11 A03.R1 | A02.U2 288.04,84.58 290.07,86.61 A02.T1 291.21,87.76 292.74,89.28 294.26,89.28 296.42,91.44 296.42,92.96 A01.R2 | A01.U2 300.74,84.58 302.77,86.61 A01.T1 | A02.N1 291.72,101.22 293.5,101.22 294.89,102.62 294.89,104.14 296.42,105.66 A01.L2 | A02.K1 294.39,109.98 296.42,112.01 A01.J2 297.56,113.16 299.08,114.68 300.61,114.68 302.77,116.84 302.77,118.36 A01.F1 | 301.24,128.14 300.74,128.14 A01.C2 | 301.24,128.14 305.69,128.14 A01.C1 | A05.C1 256.29,128.14 261.24,128.14 A04.C2 262.64,129.03 264.16,129.03 266.32,131.19 266.32,132.72 267.84,134.24 A04.A1 | v273.05,129.79 272.29,129.03 268.99,129.03 A04.C1 | 279.53,128.14 275.34,128.14 A03.C2 | 279.53,128.14 280.29,128.14 A03.C1 | A03.C1 281.69,128.14 286.64,128.14 A02.C2 288.04,128.4 292.99,128.4 A02.C1 | A03.A1 280.54,134.24 280.54,129.29 A03.C1 | A03.U2 275.34,84.58 277.37,86.61 A03.T1 | A04.U2 262.64,84.58 264.67,86.61 A04.T1 | A03.N2 271.02,99.31 271.02,97.79 268.86,95.63 267.33,95.63 265.81,94.11 A04.R1 264.67,92.96 263.78,92.08 v263.78,91.69 | v269.75,92.46 270.51,93.22 270.76,93.22 A03.R2 | A03.K1 281.69,109.98 283.72,112.01 A02.J2 283.72,113.41 283.72,118.36 A02.F2 284.86,118.62 289.81,118.62 A02.F1 | A04.K1 268.99,109.98 271.02,112.01 A03.J2 271.91,113.41 273.43,114.94 273.43,116.46 275.59,118.62 277.11,118.62 A03.F1 278.26,119.76 279.53,121.03 279.53,128.14
  Bottom 0.381: 240.16,121.03 240.16,124.08 240.92,124.84 240.92,126.36 242.44,127.89 A06.C1 | 240.16,121.03 240.16,119.76 A06.F1 | 240.16,121.03 243.46,121.03 247.27,124.84 247.27,126.36 248.79,127.89 A05.C2 | A06.K1 243.59,109.98 245.62,112.01 A05.J2 246.76,113.16 248.03,113.16 249.3,114.43 249.56,114.43 250.44,115.32 250.44,116.84 251.97,118.36 A05.F1 | A05.K1 256.29,109.98 258.32,112.01 A04.J2 259.46,113.16 260.99,114.68 262.51,114.68 264.67,116.84 264.67,118.36 A04.F1 | A02.L2 283.46,105.92 281.94,105.92 279.78,103.76 279.78,102.23 278.26,100.71 A03.N1 | A01.F2 297.31,119.76 297.31,119.89 297.69,120.27 297.69,124.46 301.24,128.02 301.24,128.14 | A22.U2 34.04,84.58 35.56,84.58 40.89,89.92 40.89,91.44 42.42,92.96 A21.R2 | A21.C2 45.59,127.89 45.59,123.57 44.83,122.81 44.83,121.28 43.31,119.76 A21.F2 | 32.89,126.62 32.89,123.57 32.13,122.81 32.13,121.28 30.61,119.76 A22.F2 | 32.89,126.62 32.89,127.89 A22.C2 | 20.19,126.62 20.19,123.57 19.43,122.81 19.43,121.28 17.91,119.76 A23.F2 | 20.19,126.62 20.19,127.89 A23.C2 | 32.89,126.62 20.19,126.62 | 25.65,58.29 21.34,58.29 B23.C2 | 25.65,58.29 27.3,56.64 v31.11,60.45 | A20.R2 55.12,92.96 53.59,91.44 53.59,89.92 48.39,84.71 47.75,84.71 47.62,84.58 46.74,84.58 A21.U2 45.59,83.44 44.07,81.92 44.07,80.39 29.97,66.29 29.97,65.79 25.78,61.59 25.78,58.42 25.65,58.29 | A20.C2 58.29,127.89 58.29,123.57 57.53,122.81 57.53,121.41 55.88,119.76 A20.F2 | 147.32,124.21 147.32,123.7 146.43,122.81 146.43,121.28 144.91,119.76 A13.F2 | 147.32,124.21 v147.32,125.35 | A12.C2 159.64,128.14 155.32,128.14 151.38,124.21 147.32,124.21
  Bottom 0.381: v166.62,126.75 168.02,128.14 172.34,128.14 A11.C2 | 184.53,129.03 180.72,129.03 179.2,130.56 v176.91,128.27 | 184.53,129.03 185.04,129.03 A10.C2 | v193.68,135.51 192.28,136.91 184.53,129.16 184.53,129.03 | A14.U2 135.38,84.84 135.38,86.36 140.72,91.69 142.24,91.69 143.76,93.22 A13.R2 | A18.C2 83.69,127.89 83.69,123.57 82.93,122.81 82.93,121.28 81.41,119.76 A18.F2 | A19.C2 70.99,127.89 70.99,123.57 70.23,122.81 70.23,121.28 68.71,119.76 A19.F2 | A16.C2 109.09,127.89 109.09,123.57 108.33,122.81 108.33,121.28 106.81,119.76 A16.F2 | A17.J2 93.22,112.01 93.22,107.06 A17.L2 | v90.81,55.37 91.69,55.37 93.09,56.77 94.61,56.77 96.14,58.29 B17.C2 97.28,59.44 97.28,60.96 102.62,66.29 103,66.29 v104.14,67.44 | v120.65,57.53 120.78,57.53 121.54,58.29 B15.C2 | A18.N2 80.52,99.31 80.52,94.36 A18.R2 | v204.98,136.53 204.6,136.53 200.41,132.33 200.41,130.81 198.88,129.29 A09.C2
I_3CYCLE  (via drill 0.61)
  Top 0.152: v218.69,75.06 222.88,70.87 222.88,68.2 238.63,52.45 238.63,48.64 247.14,40.13 248.54,40.13 B05.K2 | v118.87,97.92 125.09,97.92 128.52,94.49 129.29,94.49 143.89,79.88 147.07,79.88 v160.15,66.8 | v198.5,101.09 198.5,100.46 v220.6,78.36
  Bottom 0.152: v218.69,75.06 218.69,76.45 v220.6,78.36 228.09,85.85 228.6,85.85 244.47,101.73 244.47,101.98 248.41,105.92 249.05,105.92 250.82,107.7 250.82,108.46 249.94,109.35 A05.K2 | v118.87,97.92 91.31,70.36 89.03,70.36 84.84,66.17 83.57,66.17 68.71,51.31 68.71,49.91 B19.F2 | v160.15,66.8 160.4,66.8 194.69,101.09 v198.5,101.09
I_AC00  (via drill 0.61)
  Top 0.152: v151,101.85 153.42,101.85 183.26,72.01 183.9,72.01 v188.98,66.93 | v224.16,101.09 v228.6,101.09 | v234.95,106.17 235.71,106.17 v242.95,98.93 | v265.43,73.41 272.67,66.17 275.21,66.17 277.37,64.01 277.37,62.61 B03.B1 | v260.22,68.33 259.84,68.33 v250.06,78.11 | v237.36,66.67 235.71,66.67 230.25,72.14 229.74,72.14 222.38,79.5 220.47,79.5 213.23,86.74 213.23,87.38 v211.84,88.77
  Bottom 0.152: v151,101.85 145.54,96.39 145.54,93.09 134.49,82.04 131.19,82.04 106.81,57.66 106.81,56.26 B16.D2 | v188.98,66.93 189.99,66.93 v211.84,88.77 v224.16,101.09 | v228.6,101.09 229.87,101.09 v234.95,106.17 | v242.95,98.93 243.33,98.93 245.49,101.09 245.87,101.09 247.4,102.62 247.4,103 248.67,104.27 249.17,104.27 249.68,104.78 249.68,105.28 264.54,120.14 267.84,120.14 272.54,124.84 272.54,128.14 274.07,129.67 275.46,129.67 277.11,131.32 A03.B1 | v265.43,73.41 265.05,73.41 263.4,71.75 263.4,71.5 v260.22,68.33 | v250.06,78.11 248.16,78.11 247.78,77.72 247.78,77.09 v237.36,66.67
I_AC01  (via drill 0.61)
  Top 0.152: v212.72,142.75 214.63,142.75 v219.2,138.18 | v235.59,143 238.12,143 238.63,142.49 239.52,142.49 248.54,133.48 249.43,133.48 v250.19,132.72 | v264.29,137.29 274.07,127.51 275.46,127.51 277.11,125.86 A03.D1 278.51,125.09 280.29,123.32 281.56,123.32 282.96,121.92 v282.96,121.41 | v290.45,65.79 290.45,65.91 279.91,76.45 279.91,76.71 v258.95,97.66
  Bottom 0.152: v212.72,142.75 209.68,139.7 207.9,139.7 207.77,139.57 206.5,139.57 206.25,139.32 202.44,139.32 199.14,136.02 197.87,136.02 185.55,123.7 185.04,123.7 167.39,106.05 166.75,106.05 156.34,95.63 154.56,95.63 150.88,91.95 146.94,91.95 123.44,68.45 120.27,68.45 116.97,65.15 116.97,64.52 106.81,54.36 106.81,49.91 B16.F2 | v219.2,138.18 222.25,138.18 224.41,140.34 232.92,140.34 v235.59,143 | v250.19,132.72 250.19,133.1 251.08,133.99 252.48,133.99 255.78,137.29 v264.29,137.29 | v290.45,65.79 280.67,56.01 278.51,56.01 B03.D1 | v258.95,97.66 258.95,97.79 259.84,98.68 260.22,98.68 v282.96,121.41
I_AC02  (via drill 0.61)
  Top 0.152: v216.28,142.37 217.81,142.37 v220.6,139.57 | v233.81,142.37 234.57,142.37 v238.63,138.3 | v246.51,139.57 246.89,139.57 v267.08,119.38 | v278.64,123.83 279.15,123.83 280.29,122.68 A03.E1 283.08,120.14 284.73,120.14 289.31,115.57 v289.81,115.57 | v276.73,58.29 280.54,54.48 280.54,53.09 B03.E1 | v288.93,69.98 290.19,69.98 v290.96,69.22 | v304.29,79.76 304.29,82.17 291.72,94.74 291.72,97.16 289.43,99.44 289.43,104.01 v286,107.44
  Bottom 0.152: v216.28,142.37 210.31,136.4 206.88,136.4 205.87,135.38 205.87,134.37 197.99,126.49 194.69,126.49 182.37,114.17 181.86,114.17 180.97,113.28 180.21,113.28 172.21,105.28 170.69,105.28 166.5,101.09 162.94,101.09 161.04,99.19 160.4,99.19 139.45,78.23 139.45,77.22 128.4,66.17 128.02,66.17 106.81,44.96 106.81,43.56 B16.J2 | v220.6,139.57 223.14,139.57 224.28,140.72 232.16,140.72 v233.81,142.37 | v238.63,138.3 245.24,138.3 v246.51,139.57 | v267.08,119.38 268.1,119.38 272.54,123.83 v278.64,123.83 | v276.73,58.29 277.24,58.29 v288.93,69.98 | v290.96,69.22 292.23,69.22 293.75,70.74 294.64,70.74 297.18,73.28 297.81,73.28 v304.29,79.76 | v286,107.44 286,111.76 v289.81,115.57
I_AC03  (via drill 0.61)
  Top 0.152: v218.82,142.49 220.73,142.49 224.41,138.81 224.66,138.81 232.79,130.68 234.95,130.68 v235.33,130.3 | v242.7,137.16 243.33,137.16 254.38,126.11 254.38,121.79 v255.52,120.65 | v257.81,122.81 257.81,122.43 258.7,121.54 259.21,121.54 v274.7,106.05 | v302.89,77.09 v302.89,68.96 | v305.05,82.42 305.05,82.55 v292.48,95.12 | v295.27,101.22 295.27,103.76 288.04,111 287.53,111 284.73,113.79 283.34,113.79 281.69,115.44 A03.H1
  Bottom 0.152: v218.82,142.49 217.42,141.1 216.66,141.1 211.58,136.02 210.57,136.02 185.55,111 185.04,111 180.09,106.05 180.09,105.92 134.11,59.94 133.99,59.94 125.86,51.82 124.71,51.82 109.86,36.96 107.06,36.96 B16.L2 | v235.33,130.3 235.84,130.3 v242.7,137.16 | v255.52,120.65 255.65,120.65 v257.81,122.81 | v274.7,106.05 274.7,106.68 281.18,113.16 281.18,113.54 281.56,113.92 281.56,115.32 A03.H1 | v302.89,68.96 300.1,66.17 299.47,66.17 288.42,55.12 288.42,51.82 283.97,47.37 283.08,47.37 282.19,46.48 281.69,46.48 B03.H1 | v302.89,77.09 302.89,77.22 305.05,79.38 v305.05,82.42 | v292.48,95.12 292.48,98.42 v295.27,101.22
I_AC04  (via drill 0.61)
  Top 0.152: v130.81,47.37 131.44,47.37 146.94,31.88 150.88,31.88 151.38,31.37 152.78,31.37 v179.58,4.57 | v206.38,30.35 206.38,30.1 226.44,10.03 227.33,10.03 v230.25,7.11 | v275.72,44.45 275.97,44.45 277.11,43.31 B03.J1 | v282.32,98.68 282.07,98.93 282.07,103.76 278.26,107.57 278.26,112.01 A03.J1 | v260.6,74.3 260.6,73.79 263.78,70.61 264.92,70.61 272.92,62.61 272.92,62.1 v273.3,61.72 | v271.4,59.82 271.4,58.67 v283.46,46.61
  Bottom 0.152: v130.81,47.37 125.35,47.37 108.58,30.61 107.06,30.61 B16.N2 | v179.58,4.57 181.74,6.73 182.37,6.73 189.87,14.22 190.25,14.22 v206.38,30.35 | v230.25,7.11 232.66,7.11 234.7,9.14 234.7,9.4 247.27,21.97 248.92,21.97 264.54,37.59 268.86,37.59 v275.72,44.45 | v282.32,98.68 282.32,96.52 280.67,94.87 280.54,94.87 278.89,93.22 278.89,93.09 275.21,89.41 274.83,89.41 273.94,88.52 273.94,88.14 270.13,84.33 270,84.33 269.62,83.95 269.62,83.31 v260.6,74.3 | v271.4,59.82 v273.3,61.72 | v283.46,46.61 283.21,46.61 281.56,44.96 280.16,44.96 278.51,43.31 B03.J1
I_AC05  (via drill 0.61)
  Top 0.152: v119,15.88 111.51,23.37 107.06,23.37 B16.R2 | v172.21,62.48 173.48,62.48 178.69,57.28 179.2,57.28 189.61,46.86 189.74,46.86 190.12,46.48 190.12,46.1 200.41,35.81 200.41,35.18 205.99,29.59 206.38,29.59 226.31,9.65 226.57,9.65 229.87,6.35 231.01,6.35 v236.09,1.27 | v285.75,30.23 281.56,34.42 280.16,34.42 278.51,36.07 B03.L1 | v271.91,114.68 277.37,109.22 277.37,107.06 A03.L1 | v260.35,103 259.08,103 254.51,107.57 253.37,107.57 249.94,111 249.43,111 v242.95,117.47 | v229.24,106.43 228.6,106.43 227.58,107.44 223.9,107.44 v220.73,110.62
  Bottom 0.152: v119,15.88 125.6,15.88 v172.21,62.48 172.47,62.87 189.99,80.39 189.99,80.52 191.77,82.3 191.9,82.3 208.15,98.55 208.66,98.55 212.98,102.87 213.49,102.87 220.73,110.11 v220.73,110.62 | v236.09,1.27 241.94,1.27 242.44,0.76 256.92,0.76 279.91,23.75 279.91,24.26 285.75,30.1 v285.75,30.23 | v271.91,114.68 271.78,114.68 270.38,113.28 270.38,113.03 268.22,110.87 267.97,110.87 260.86,103.76 260.86,103.5 v260.35,103 | v242.95,117.47 240.28,117.47 v229.24,106.43
I_AC06  (via drill 0.61)
  Top 0.152: v184.02,138.43 192.79,138.43 204.09,127.13 204.6,127.13 220.09,111.63 222.12,111.63 222.38,111.38 223.65,111.38 227.2,107.82 228.35,107.82 v228.47,107.7 | v252.73,129.54 252.98,129.54 277.24,105.28 278.64,105.28 280.29,103.63 A03.M1 | v270.89,20.83 270.89,20.32 v271.78,19.43 | v260.1,8.38 256.79,8.38 249.81,15.37 247.27,15.37 v247.01,15.62 | v232.28,1.65 232.28,2.29 231.39,3.17 230.76,3.17 v208.28,25.65 | v180.72,3.43 179.58,3.43 169.29,13.72 168.91,13.72 160.91,21.72 157.86,21.72 157.61,21.97 157.35,21.97 156.97,22.35 153.92,22.35 v135,41.27 | v126.49,38.1 126.49,38.73 122.3,42.93 122.3,43.43 v103,62.74
  Bottom 0.152: 103.12,62.61 104.14,63.63 105.28,63.63 116.46,74.8 117.6,74.8 131.19,88.39 134.49,88.39 180.47,134.37 180.47,134.87 v184.02,138.43 | 103.12,62.61 96.52,56.01 94.36,56.01 B17.D2 | v228.47,107.7 230,107.7 240.16,117.86 240.41,117.86 241.68,119.13 242.32,119.13 v252.73,129.54 | v270.89,20.83 280.54,30.48 280.54,32.64 B03.M1 | v271.78,19.43 271.14,19.43 v260.1,8.38 | v247.01,15.62 247.01,15.11 233.93,2.03 232.66,2.03 v232.28,1.65 | v208.28,25.65 208.15,25.65 206.88,24.38 206.88,24 205.87,22.99 205.23,22.99 189.74,7.49 187.2,7.49 186.82,7.11 185.55,7.11 184.02,5.59 182.88,5.59 v180.72,3.43 | v135,41.27 131.83,41.27 129.16,38.61 127,38.61 v126.49,38.1 | v103,62.74 103.12,62.61
I_AC07  (via drill 0.61)
  Top 0.152: v257.56,4.19 248.28,4.19 v244.35,8.13 | v233.81,1.27 208.66,26.42 207.52,26.42 v204.34,29.59 | v176.15,5.21 171.07,5.21 160.91,15.37 154.56,15.37 v149.86,20.07 | v136.14,13.21 133.1,13.21 130.18,16.13 129.92,16.13 122.94,23.11 121.41,23.11 106.93,37.59 103.63,37.59 102.11,39.12 102.11,42.42 97.41,47.12 96.01,47.12 94.36,48.77 B17.F2 | v258.95,110.87 265.56,104.27 268.86,104.27 274.83,98.3 276.61,98.3 277.62,97.28 280.29,97.28 A03.P1 | v228.6,84.71 v230.12,86.23 | v195.96,47.62 195.96,46.61 v205.99,36.58
  Bottom 0.152: v257.56,4.19 263.4,10.03 265.68,10.03 279.53,23.88 279.53,24.38 280.54,25.4 280.54,26.29 B03.P1 | v244.35,8.13 240.66,8.13 v233.81,1.27 | v176.15,5.21 180.97,10.03 183.13,10.03 193.8,20.7 193.8,21.08 194.18,21.46 195.07,21.46 203.2,29.59 v204.34,29.59 204.6,29.97 205.99,31.37 v205.99,36.58 | v149.86,20.07 148.72,20.07 145.03,16.38 139.32,16.38 v136.14,13.21 | v258.95,110.87 258.95,110.24 254.38,105.66 253.87,105.66 253.11,104.9 252.6,104.9 246.63,98.93 246.38,98.93 244.86,97.41 244.86,97.16 243.46,95.76 239.65,95.76 v230.12,86.23 | v228.6,84.71 228.6,84.2 225.93,81.53 225.93,81.15 219.07,74.3 218.69,74.3 210.06,65.66 210.06,61.72 v195.96,47.62
I_AC08  (via drill 0.61)
  Top 0.152: v131.06,2.41 110.74,22.73 105.79,22.73 97.92,30.61 97.92,33.91 95.76,36.07 95.76,36.58 94.11,38.23 94.11,42.16 B17.J2 | v179.96,12.32 179.96,12.06 181.99,10.03 186.06,10.03 186.94,9.14 188.21,9.14 v195.07,2.29 | v200.53,5.71 204.22,5.71 v208.66,1.27 | v226.19,2.79 v219.84,2.79 | v247.65,21.21 248.79,22.35 249.3,22.35 253.11,18.54 254.76,18.54 v265.94,7.37 | v297.56,72.52 292.74,77.34 292.1,77.34 286.51,82.93 285.24,82.93 281.43,86.74 281.43,89.79 A03.S1 | v283.85,60.33 283.85,58.93 289.31,53.47 289.31,53.34 v299.72,42.93
  Bottom 0.152: v131.06,2.41 159.77,2.41 162.43,5.08 163.45,5.08 163.7,5.33 171.83,5.33 176.53,10.03 177.67,10.03 v179.96,12.32 | v195.07,2.29 197.1,2.29 v200.53,5.71 | v208.66,1.27 215.39,1.27 215.9,0.76 217.81,0.76 v219.84,2.79 | v226.19,2.79 229.24,2.79 v247.65,21.21 | v265.94,7.37 266.06,7.37 277.24,18.54 278.64,18.54 280.29,20.19 B03.S1 281.69,21.08 283.34,22.73 284.73,22.73 295.78,33.78 295.78,37.08 299.72,41.02 v299.72,42.93 | v297.56,72.52 296.93,72.52 294.77,70.36 293.88,70.36 289.69,66.17 289.69,65.79 284.73,60.83 284.35,60.83 v283.85,60.33
I_AC09  (via drill 0.61)
  Top 0.152: v104.52,38.48 114.3,38.48 v117.35,35.43 117.73,35.18 130.18,22.73 v134.24,22.73 | v224.79,139.57 231.9,139.57 v232.92,138.56 | v239.01,143.26 239.27,143.26 248.67,133.86 250.82,133.86 v251.46,133.22 | v254.63,133.22 v263.52,124.33 | v249.56,31.24 249.56,29.34 v259.33,19.56 | v241.17,2.03 240.28,2.03 v230.12,12.19 | v217.04,2.54 216.41,2.54 v215.26,3.68 | v205.87,2.54 201.04,2.54 v198.63,4.95 | v193.8,2.16 183.13,2.16 179.96,5.33 179.71,5.33 v151.38,33.66
  Bottom 0.152: v104.52,38.48 103.63,37.59 99.44,37.59 98.81,36.96 94.36,36.96 B17.L2 | v117.35,35.43 120.27,35.43 137.92,53.09 138.18,53.09 161.16,76.07 161.29,76.07 161.67,76.45 161.67,77.22 169.16,84.71 169.16,84.96 187.96,103.76 187.96,103.89 188.34,104.27 188.98,104.27 210.19,125.48 210.44,125.48 210.82,125.86 211.07,125.86 v224.79,139.57 | v232.92,138.56 234.31,138.56 v239.01,143.26 | v251.46,133.22 v254.63,133.22 | v263.52,124.33 270.13,124.33 270.76,124.97 A03.D2 | v249.56,31.24 264.03,45.72 264.03,49.78 265.68,51.44 266.32,51.44 267.21,52.32 267.21,52.96 269.37,55.12 270.76,55.12 B03.D2 | v259.33,19.56 258.7,19.56 250.95,11.81 250.95,10.67 243.84,3.56 242.7,3.56 v241.17,2.03 | v230.12,12.19 226.44,12.19 225.93,11.68 225.93,11.43 v217.04,2.54 | v215.26,3.68 212.09,3.68 211.33,2.92 206.25,2.92 v205.87,2.54 | v198.63,4.95 196.6,4.95 v193.8,2.16 | v151.38,33.66 150.11,33.66 147.57,31.11 147.07,31.11 145.03,29.08 140.59,29.08 v134.24,22.73
I_AC10  (via drill 0.61)
  Top 0.152: v122.81,3.17 96.27,29.72 94.36,29.72 B17.N2 | v180.85,31.24 183.13,31.24 193.17,21.21 193.17,20.95 194.18,19.94 194.82,19.94 v207.9,6.86 | v222.25,23.88 v222.25,21.84 | v238.38,40.01 239.78,40.01 242.32,37.47 242.95,37.47 247.01,33.4 247.52,33.4 248.67,32.26 v251.84,32.26 | v305.05,100.46 290.7,114.81 286.77,114.81 280.16,121.41 275.84,121.41 275.46,121.79 275.34,121.79 A03.E2 | v304.8,76.33 v293.37,87.76 | v280.67,48.26 280.42,48.26 278.38,50.29 276.99,50.29 275.34,51.94 B03.E2
  Bottom 0.152: v122.81,3.17 149.73,3.17 151.13,4.57 154.43,4.57 165.23,15.37 165.23,15.62 v180.85,31.24 | v207.9,6.86 207.9,7.49 214.76,14.35 215.39,14.35 216.79,15.75 217.3,15.75 219.84,18.29 219.84,19.43 v222.25,21.84 | v222.25,23.88 224.03,25.65 224.66,25.65 232.66,33.66 232.66,34.16 238.38,39.88 v238.38,40.01 | v251.84,32.26 256.16,32.26 256.67,32.77 256.67,36.07 261.37,40.77 264.67,40.77 272.54,48.64 272.54,50.04 274.19,51.69 B03.E2 | v305.05,100.46 305.05,100.08 300.61,95.63 300.61,95 v293.37,87.76 | v304.8,76.33 304.8,72.52 280.67,48.39 v280.67,48.26
I_AC11  (via drill 0.61)
  Top 0.152: v196.85,117.09 199.77,117.09 v205.87,111 | v241.55,143 250.82,143 256.92,136.91 256.92,136.14 257.68,135.38 257.94,135.38 v275.84,117.47 | v263.27,30.86 263.27,30.35 270.89,22.73 271.27,22.73 272.92,21.08 273.05,21.08 273.43,20.7 v273.43,19.3 | v246.63,4.7 244.22,4.7 243.84,5.08 243.33,5.08 v226.44,21.97 | v207.77,5.59 206.63,5.59 205.49,6.73 204.85,6.73 v203.71,7.87 | v197.23,1.27 172.34,1.27 v164.72,8.89 | v159.89,8.89 145.03,8.89 144.65,8.51 143.26,8.51 137.79,13.97 137.54,13.97 v113.79,37.72
  Bottom 0.152: 113.03,38.48 124.84,50.29 129.29,50.29 157.35,78.36 158.12,78.36 v196.85,117.09 | 113.03,38.48 98.81,24.26 94.36,24.26 B17.R2 | v205.87,111 207.9,111 209.04,112.14 209.04,112.65 210.82,114.43 211.33,114.43 218.57,121.67 218.57,122.81 219.84,124.08 220.98,124.08 228.09,131.19 228.09,133.99 228.85,134.75 228.85,135.25 229.62,136.02 232.28,136.02 235.2,138.94 235.71,138.94 238.63,141.86 240.41,141.86 v241.55,143 | v275.84,117.47 275.84,117.35 275.08,116.59 A03.H2 | v263.27,30.86 276.86,44.45 275.72,45.59 275.34,45.59 B03.H2 | v273.43,19.3 272.8,19.3 272.16,18.67 271.02,18.67 264.03,11.68 264.03,11.18 260.48,7.62 259.71,7.62 258.95,6.86 257.81,6.86 255.65,4.7 v246.63,4.7 | v226.44,21.97 226.44,21.59 214.88,10.03 212.22,10.03 v207.77,5.59 | v203.71,7.87 203.71,7.75 v197.23,1.27 | v164.72,8.89 v159.89,8.89 | v113.79,37.72 113.03,38.48
I_ACCEPT  (via drill 0.61)
  Top 0.152: v151.38,13.21 145.8,18.8 145.8,19.43 127.25,37.97 127.25,38.48 122.68,43.05 122.68,45.34 B15.H2 | v198.75,56.64 198.75,56.01 207.14,47.62 207.14,46.99 207.26,46.86 207.26,45.85 219.96,33.15 | 219.96,33.15 219.96,32.77 v227.33,25.4 | v258.95,21.46 259.33,21.08 261.24,21.08 B04.S2 | v249.17,11.68 248.92,11.68 v233.93,26.67 | v232.28,63.25 233.68,63.25 237.62,59.31 237.62,57.78 v238.51,56.9 | v221.11,34.29 219.96,33.15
